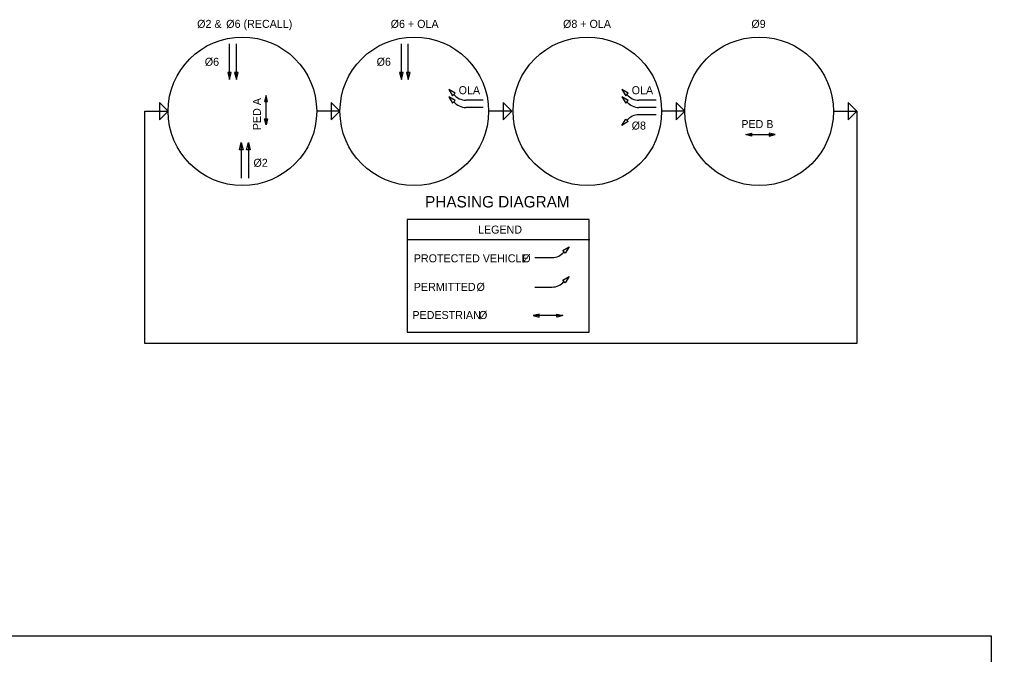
# Model space of a CAD drawing. Extents: x 680 to 2132, y 0 to 656.
# Drawn here: x 1020 to 1360, y 433.6 to 655.8 of the extents above; entities that cross this region are included whole.
import ezdxf

# ---------------------------------------------------------------- set-up
doc = ezdxf.new("R2010")
doc.units = 0
for name, color, linetype in [('SH_Cut_Line', 7, 'Continuous'), ('SH_Data', 7, 'Continuous'), ('SH_Text', 7, 'Continuous')]:
    doc.layers.add(name, color=color, linetype=linetype)

msp = doc.modelspace()

# ---------------------------------------------------------------- linework, layer by layer
at = {"layer": 'SH_Cut_Line'}
msp.add_lwpolyline([(680, 0), (1360, 0), (1360, 440), (680, 440)], close=True, dxfattribs=at)
at = {"layer": 'SH_Data'}
for p, q in [((1093.46, 634.82), (1093.46, 647.28)), ((1095.87, 634.82), (1095.87, 647.28)), ((1153.57, 634.82), (1153.57, 647.28)), ((1155.97, 634.82), (1155.97, 647.28)), ((1106.24, 618.94), (1106.24, 629.21)), ((1182.2, 627.57), (1176.08, 627.58)), ((1242.72, 627.57), (1236.61, 627.57)), ((1132.1, 623.69), (1123.98, 623.69)), ((1182.2, 625.03), (1176.08, 625.04)), ((1192.21, 623.69), (1184.08, 623.69)), ((1242.72, 625.03), (1236.61, 625.03)), ((1242.72, 622.49), (1236.61, 622.49)), ((1252.73, 623.69), (1244.61, 623.69)), ((1274.01, 615.54), (1284.27, 615.54)), ((1097.56, 612.73), (1097.56, 600.28)), ((1100.1, 612.73), (1100.1, 600.28)), ((1155.5, 578.8), (1219.54, 578.8)), ((1200.22, 572.53), (1206.33, 572.53)), ((1200.22, 562.19), (1206.33, 562.19)), ((1210, 552.23), (1199.73, 552.23))]:
    msp.add_line(p, q, dxfattribs=at)
for points in [[(1092.84, 637.32), (1093.46, 634.82), (1094.09, 637.32)], [(1095.24, 637.32), (1095.87, 634.82), (1096.49, 637.32)], [(1152.94, 637.32), (1153.57, 634.82), (1154.19, 637.32)], [(1155.35, 637.32), (1155.97, 634.82), (1156.6, 637.32)], [(1106.76, 627.12), (1106.24, 629.21), (1105.72, 627.12)], [(1172.4, 630), (1170.18, 631.32), (1171.51, 629.11)], [(1232.92, 629.99), (1230.71, 631.32), (1232.04, 629.11)], [(1071.99, 623.69), (1068.96, 626.72), (1068.96, 620.66)], [(1132.1, 623.69), (1129.07, 626.72), (1129.07, 620.66)], [(1172.4, 627.46), (1170.18, 628.78), (1171.51, 626.57)], [(1192.21, 623.69), (1189.18, 626.72), (1189.17, 620.66)], [(1232.92, 627.45), (1230.71, 628.78), (1232.04, 626.57)], [(1252.73, 623.69), (1249.7, 626.72), (1249.7, 620.66)], [(1312.84, 623.69), (1309.81, 626.72), (1309.8, 620.66)], [(1106.76, 621.02), (1106.24, 618.94), (1105.72, 621.02)], [(1232.92, 620.07), (1230.71, 618.74), (1232.04, 620.95)], [(1276.09, 615.02), (1274.01, 615.54), (1276.09, 616.06)], [(1282.19, 615.02), (1284.27, 615.54), (1282.19, 616.06)], [(1096.93, 610.23), (1097.56, 612.73), (1098.19, 610.23)], [(1099.47, 610.23), (1100.1, 612.73), (1100.72, 610.23)], [(1219.32, 585.8), (1155.55, 585.8), (1155.55, 546.47), (1219.32, 546.47)], [(1210.02, 574.95), (1212.23, 576.27), (1210.91, 574.07)], [(1210.02, 564.61), (1212.24, 565.93), (1210.91, 563.73)], [(1201.82, 552.75), (1199.73, 552.23), (1201.82, 551.71)], [(1207.91, 552.75), (1210, 552.23), (1207.91, 551.71)]]:
    msp.add_lwpolyline(points, close=True, dxfattribs=at)
msp.add_lwpolyline([(1304.72, 623.69), (1312.84, 623.69), (1312.84, 542.46), (1063.87, 542.46), (1063.87, 623.69), (1071.99, 623.69)], dxfattribs=at)
for centre in [(1097.98, 623.69), (1158.09, 623.69), (1218.62, 623.69), (1278.72, 623.69)]:
    msp.add_circle(centre, 25.99, dxfattribs=at)
for centre, start, end in [((1176.09, 632.88), 218.7864, 269.9871), ((1236.61, 632.87), 218.7864, 269.9871), ((1176.09, 630.34), 218.7864, 269.9871), ((1236.61, 630.33), 218.7864, 269.9871), ((1236.61, 617.19), 90.0129, 141.2136), ((1206.33, 577.83), 270.0129, 321.2136), ((1206.33, 567.49), 270, 321.2007)]:
    msp.add_arc(centre, 5.3, start, end, dxfattribs=at)

# ---------------------------------------------------------------- texts
at = {"layer": 'SH_Text'}
for s, height, p in [('Ø', 2.8, (1082.16, 652.88)), ('2 & ', 2.8, (1085.08, 652.88)), ('Ø', 2.8, (1092.32, 652.88)), ('6 (RECALL)', 2.8, (1095.25, 652.88)), ('Ø', 2.8, (1149.84, 652.88)), ('6 + OLA', 2.8, (1152.76, 652.88)), ('Ø', 2.8, (1210.12, 652.88)), ('8 + OLA', 2.8, (1213.04, 652.88)), ('Ø', 2.8, (1276, 652.88)), ('9', 2.8, (1278.92, 652.88)), ('Ø6', 2.8, (1084.83, 639.62)), ('Ø6', 2.8, (1144.93, 639.62)), ('OLA', 2.8, (1173.61, 629.67)), ('OLA', 2.8, (1234.13, 629.66)), ('Ø8', 2.8, (1234.13, 617.29)), ('PED B', 2.8, (1272.48, 617.83)), ('Ø', 2.8, (1101.85, 604.27)), ('2', 2.8, (1104.77, 604.27)), ('PHASING DIAGRAM', 4, (1161.89, 590.04)), ('LEGEND', 2.8, (1180.39, 580.9)), ('PROTECTED VEHICLE ', 2.8, (1157.93, 570.85)), ('Ø', 2.8, (1195.88, 570.85)), ('PERMITTED ', 2.8, (1157.93, 560.85)), ('Ø', 2.8, (1179.87, 560.85)), ('PEDESTRIAN ', 2.8, (1157.44, 551.01)), ('Ø', 2.8, (1180.75, 551.01))]:
    msp.add_text(s, height=height, dxfattribs=at).set_placement(p)
msp.add_text('PED A', height=2.8, rotation=90, dxfattribs=at).set_placement((1104.46, 617.08))

doc.saveas('drawing.dxf')
